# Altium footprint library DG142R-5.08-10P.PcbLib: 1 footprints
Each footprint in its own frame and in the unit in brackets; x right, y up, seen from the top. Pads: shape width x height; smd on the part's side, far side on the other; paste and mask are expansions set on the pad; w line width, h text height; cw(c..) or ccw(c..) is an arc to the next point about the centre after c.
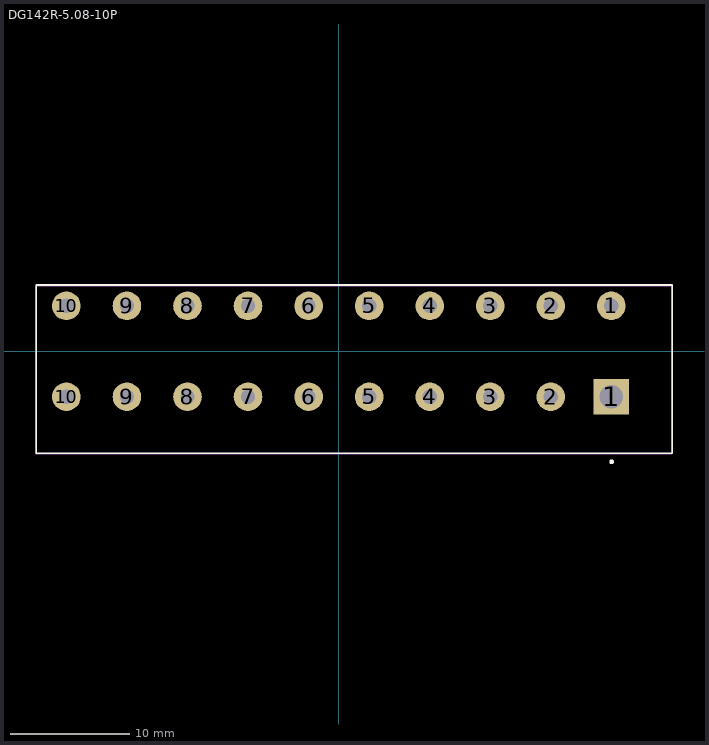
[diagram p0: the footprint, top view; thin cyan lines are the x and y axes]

## DG142R-5.08-10P [mm]
pads (20):
  rect 3x3 hole 2: 1(22.86,-3.81)
  round 2.4 hole 1.2: 1(22.86,3.81) 2(17.78,-3.81) 2(17.78,3.81) 3(12.7,-3.81) 3(12.7,3.81) 4(7.62,-3.81) 4(7.62,3.81) 5(2.54,-3.81) 5(2.54,3.81) 6(-2.54,-3.81) 6(-2.54,3.81) 7(-7.62,-3.81) 7(-7.62,3.81) 8(-12.7,-3.81) 8(-12.7,3.81) 9(-17.78,-3.81) 9(-17.78,3.81) 10(-22.86,-3.81) 10(-22.86,3.81)
Top Overlay:
  circle w0.2: c22.885,-9.271 r0.1
  lines w0.127: -25.4,-8.56 27.965,-8.56 27.965,5.563 -25.4,5.563 -25.4,-8.56
Mechanical 13:
  lines w0.127: -25.425,-8.611 -25.425,5.512 27.94,5.512 27.94,-8.611 -25.425,-8.611
3D body "DG142R-5.08-10P.stp": height 13.6, standoff -3.3, extent -25.375,-8.712 27.965,5.39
